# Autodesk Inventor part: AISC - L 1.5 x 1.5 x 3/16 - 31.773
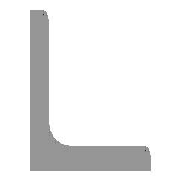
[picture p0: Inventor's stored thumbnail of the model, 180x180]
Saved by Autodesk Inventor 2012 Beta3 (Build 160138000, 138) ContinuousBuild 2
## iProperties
_CCFamilyMember: 5
_CCFamilyDisplayName: ANSI L (Equal angles) - Angle Steel
_FrameMemberDoc: Frame Member File
_Version: 15.0.0
_GetPNFromCC: 1
Created: 2010-11
Part Number: AISC - L 1.5 x 1.5 x 3/16 - 31.773
Material: Steel, Mild
Description: Angle Steel
Document SubType Name: Modeling
Standard: ANSI
Designer: Beta-8540w
Standards Organization: ANSI
Language: en-US
Size Designation: L 1.5 x 1.5 x 3/16
Categories: <MemberInstance><Categories><Category DisplayName="Structural Shapes" InternalName="089c4875-fa83-4c05-b084-43b9cc11f5ed" Mnemonic="GRDR"><CategoryParameter Dis
Stock Number: L 1.5 x 1.5 x 3/16
Density: 7.86 g/cm^3
IsCustomPart: 1
G_L: 31.773 in
G_W: 1.500 in
G_H: 1.500 in
+3B2E30B5-4963-484D-8D95-D946A704ABD9+CUTDETAIL1: Cut
Author: Beta-8540w
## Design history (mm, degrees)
node "Start plane"
node "End plane"
sketch "Sketch"
  geometry: L1 (38.1, 0)-(0, 0); L2 (0, 0)-(0, 38.1); L3 (0, 38.1)-(2.476, 38.1); L4 (4.762, 35.814)-(4.762, 9.589); L5 (9.588, 4.763)-(35.814, 4.763); L6 (38.1, 2.477)-(38.1, 0); L7 (0, -11.041)-(0, 31.538); L8 (-11.041, 0)-(31.538, 0); L9 (0, 48.496)-(0, -20.964) reference; L10 (-20.964, 0)-(48.496, 0) reference; A1 r 4.826 centre (9.588, 9.589) between (4.762, 9.589) and (9.588, 4.763); A2 r 2.286 centre (2.476, 35.814) between (4.762, 35.814) and (2.476, 38.1); A3 r 2.286 centre (35.814, 2.477) between (38.1, 2.477) and (35.814, 4.763); 3 further points
  constraints: 16 end point, 6 point on circle, 6 point on line, 6 tangent, 4 parallel, 3 centre point, 2 collinear, 1 equal radius, 1 horizontal, 1 perpendicular
  dimensions: "d0" = 38.1 distance between parallel lines of L6 L2 (= G_H); "d1" = 38.1 distance between parallel lines of L3 L1 (= G_H); "d2" = 4.7625 distance between parallel lines of L2 L4 (= G_T); "d3" = 4.7625 distance between parallel lines of L1 L5 (= G_T); "d10" = 0 distance between parallel lines of L7 L2 (computed from ex); "d11" = 0 distance between parallel lines of L8 L1 (computed from d10); "d14" = 4.826 radius of A1 (= G_IR); "d15" = 2.286 radius of A2 (= G_ER)
extrude "Body" new body sketch "Sketch" stored distance "d4" = 807.0404 (= G_L); taper "d5" = 0 deg
node "Driven Length"
  sketch "Sketch3"
    geometry: L1 (0, 0)-(10, 0) reference
    constraints: 2 end point, 1 horizontal
  workplane "Work Plane3"
  sketch "Sketch4"
    geometry: L1 (-2, 0)-(12, 0) reference; L2 (-2, 807.04)-(12, 807.04) reference
    dimensions: "d17" = 807.0404 distance between parallel lines of L1 L2 (derived)
workplane "Work Plane4"
split "Split1"
body "Solid1"
other parameters: "G_H" = 38.1 [user parameter; used in 2 equation terms], "G_T" = 4.7625 [user parameter; used in 2 equation terms], "G_ER" = 2.286 [user parameter; used in 1 equation term], "G_IR" = 4.826 [user parameter; used in 1 equation term], "G_L" = 807.0404 (= d17) [user parameter; used in 1 equation term], "ex" = 0 [user parameter; used in 1 equation term], "G_OFFSET_START" = 0 [user parameter; used in 1 equation term], "G_OFFSET_END" = -29.72503 [user parameter; used in 1 equation term], "d12" = 0 (computed from G_OFFSET_START), "d13" = 807.0404 (= G_OFFSET_END + B_L), "B_L" = 836.76542 [user parameter; used in 1 equation term], "d16" = 90 deg, "MAS" = 0.26787 [user parameter]
